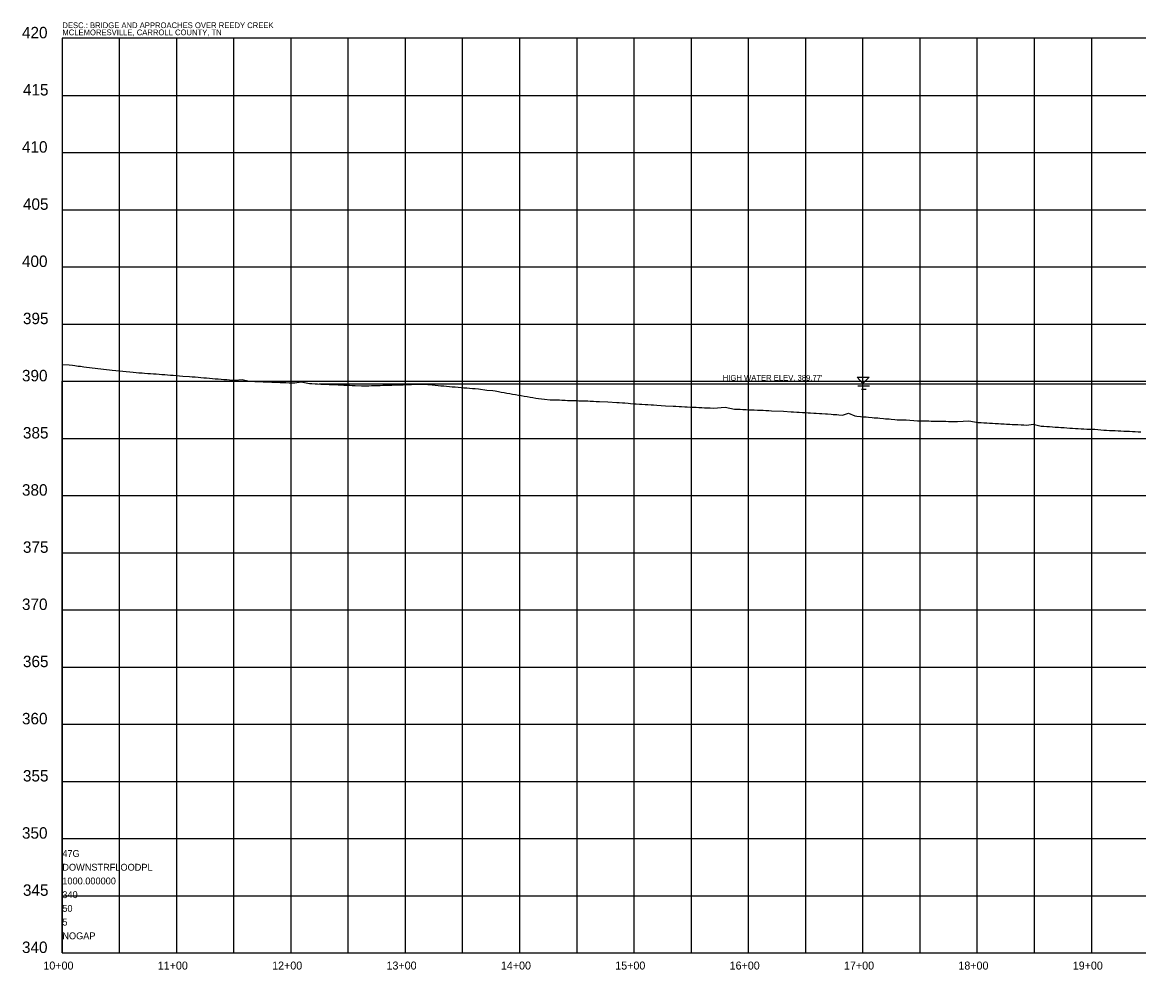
# Model space of a CAD drawing. Extents: x 1189978 to 1314812, y 571533 to 629339.
# Drawn here: x 1227570 to 1228546, y 623630 to 624459 of the extents above; entities that cross this region are included whole.
import ezdxf

# ---------------------------------------------------------------- set-up
doc = ezdxf.new("R2010")
doc.units = 0
for name, color, linetype in [('DESIGN - SHEET - Corner Text', 7, 'Continuous'), ('DESIGN - SHEET - Light Grid', 7, 'Continuous'), ('SURVEY - DRAINAGE - Pipes and Culverts Text', 7, 'Continuous'), ('SURVEY - PROFILE - Drainage - Bridge Hydraulic Data with Text', 7, 'Continuous'), ('SURVEY - PROFILE - Project Information and Notes', 7, 'Continuous')]:
    doc.layers.add(name, color=color, linetype=linetype)

msp = doc.modelspace()

# ---------------------------------------------------------------- linework, layer by layer
at = {"layer": 'DESIGN - SHEET - Light Grid'}
for p, q in [((1231404.88, 624444.99), (1227604.88, 624444.99)), ((1227604.88, 624444.99), (1227604.88, 623644.99)), ((1227654.88, 623644.99), (1227654.88, 624444.99)), ((1227704.88, 623644.99), (1227704.88, 624444.99)), ((1227754.88, 623644.99), (1227754.88, 624444.99)), ((1227804.88, 623644.99), (1227804.88, 624444.99)), ((1227854.88, 623644.99), (1227854.88, 624444.99)), ((1227904.88, 623644.99), (1227904.88, 624444.99)), ((1227954.88, 623644.99), (1227954.88, 624444.99)), ((1228004.88, 623644.99), (1228004.88, 624444.99)), ((1228054.88, 623644.99), (1228054.88, 624444.99)), ((1228104.88, 623644.99), (1228104.88, 624444.99)), ((1228154.88, 623644.99), (1228154.88, 624444.99)), ((1228204.88, 623644.99), (1228204.88, 624444.99)), ((1228254.88, 623644.99), (1228254.88, 624444.99)), ((1228304.88, 623644.99), (1228304.88, 624444.99)), ((1228354.88, 623644.99), (1228354.88, 624444.99)), ((1228404.88, 623644.99), (1228404.88, 624444.99)), ((1228454.88, 623644.99), (1228454.88, 624444.99)), ((1228504.88, 623644.99), (1228504.88, 624444.99)), ((1227604.88, 624394.99), (1231404.88, 624394.99)), ((1227604.88, 624344.99), (1231404.88, 624344.99)), ((1227604.88, 624294.99), (1231404.88, 624294.99)), ((1227604.88, 624244.99), (1231404.88, 624244.99)), ((1227604.88, 624194.99), (1231404.88, 624194.99)), ((1227604.88, 623644.99), (1227604.88, 624144.99)), ((1227604.88, 624144.99), (1231404.88, 624144.99)), ((1227604.88, 624094.99), (1231404.88, 624094.99)), ((1227604.88, 624044.99), (1231404.88, 624044.99)), ((1227604.88, 623994.99), (1231404.88, 623994.99)), ((1227604.88, 623944.99), (1231404.88, 623944.99)), ((1227604.88, 623894.99), (1231404.88, 623894.99)), ((1227604.88, 623844.99), (1231404.88, 623844.99)), ((1227604.88, 623794.99), (1231404.88, 623794.99)), ((1227604.88, 623744.99), (1231404.88, 623744.99)), ((1227604.88, 623694.99), (1231404.88, 623694.99)), ((1227604.88, 623644.99), (1231398.82, 623644.99)), ((1227604.88, 623644.99), (1227604.88, 623644.99)), ((1227604.88, 623644.99), (1231404.88, 623644.99))]:
    msp.add_line(p, q, dxfattribs=at)
at = {"layer": 'SURVEY - DRAINAGE - Pipes and Culverts Text'}
for p, q in [((1228299.7, 624148.55), (1228310.19, 624148.75)), ((1228299.7, 624148.55), (1228310.19, 624148.75)), ((1228304.88, 624142.96), (1228299.7, 624148.55)), ((1228304.88, 624142.96), (1228299.7, 624148.55)), ((1228310.19, 624148.75), (1228304.88, 624142.96)), ((1228310.19, 624148.75), (1228304.88, 624142.96)), ((1227829.3, 624142.69), (1231224.2, 624142.69)), ((1228300.52, 624140.93), (1228310.6, 624140.93)), ((1228300.52, 624140.93), (1228310.6, 624140.93)), ((1228303.61, 624138.26), (1228307.72, 624138.26)), ((1228303.61, 624138.26), (1228307.72, 624138.26))]:
    msp.add_line(p, q, dxfattribs=at)
at = {"layer": 'SURVEY - PROFILE - Drainage - Bridge Hydraulic Data with Text'}
msp.add_lwpolyline([(1227604.88, 624159.74), (1227610.85, 624159.41), (1227613.66, 624159), (1227615.87, 624158.77), (1227618.61, 624158.37), (1227620.89, 624158.13), (1227623.56, 624157.75), (1227625.91, 624157.5), (1227628.51, 624157.13), (1227630.93, 624156.88), (1227633.46, 624156.52), (1227635.94, 624156.26), (1227638.42, 624155.91), (1227640.96, 624155.65), (1227643.38, 624155.31), (1227645.98, 624155.04), (1227648.34, 624154.71), (1227657.87, 624153.86), (1227666.83, 624152.91), (1227669.55, 624152.68), (1227671.84, 624152.54), (1227674.54, 624152.31), (1227676.84, 624152.16), (1227679.53, 624151.94), (1227681.85, 624151.79), (1227684.52, 624151.56), (1227686.85, 624151.42), (1227689.51, 624151.19), (1227691.86, 624151.04), (1227694.49, 624150.82), (1227696.87, 624150.67), (1227699.48, 624150.45), (1227701.88, 624150.3), (1227704.47, 624150.08), (1227710.18, 624149.5), (1227716.09, 624149.21), (1227718.54, 624148.95), (1227721.08, 624148.8), (1227723.55, 624148.54), (1227726.07, 624148.39), (1227728.57, 624148.12), (1227731.07, 624147.97), (1227733.59, 624147.7), (1227736.06, 624147.56), (1227738.61, 624147.29), (1227741.05, 624147.14), (1227743.62, 624146.87), (1227746.05, 624146.72), (1227748.64, 624146.44), (1227751.04, 624146.3), (1227753.65, 624146.02), (1227756.04, 624145.87), (1227762.17, 624146.66), (1227768.13, 624145.1), (1227770.69, 624144.98), (1227773.15, 624144.9), (1227775.65, 624144.78), (1227778.16, 624144.71), (1227780.61, 624144.59), (1227783.17, 624144.52), (1227785.56, 624144.4), (1227788.19, 624144.32), (1227790.52, 624144.21), (1227793.2, 624144.13), (1227795.48, 624144.03), (1227798.21, 624143.95), (1227800.44, 624143.84), (1227803.22, 624143.76), (1227805.4, 624143.66), (1227808.24, 624143.58), (1227813.78, 624144.48), (1227821.01, 624143.07), (1227823.11, 624142.96), (1227825.99, 624142.85), (1227828.12, 624142.74), (1227830.97, 624142.63), (1227833.13, 624142.51), (1227835.96, 624142.41), (1227838.14, 624142.29), (1227840.94, 624142.19), (1227843.14, 624142.07), (1227845.92, 624141.96), (1227848.15, 624141.85), (1227850.9, 624141.74), (1227853.16, 624141.62), (1227855.88, 624141.52), (1227858.17, 624141.4), (1227860.86, 624141.29), (1227866.39, 624141.17), (1227872.86, 624141.18), (1227875.22, 624141.31), (1227877.86, 624141.32), (1227880.22, 624141.45), (1227882.85, 624141.46), (1227885.22, 624141.58), (1227887.85, 624141.6), (1227890.21, 624141.72), (1227892.85, 624141.74), (1227895.21, 624141.86), (1227897.84, 624141.88), (1227900.21, 624142), (1227902.84, 624142.03), (1227905.21, 624142.14), (1227907.84, 624142.17), (1227910.21, 624142.28), (1227920.26, 624142.41), (1227928.34, 624141.87), (1227930.9, 624141.57), (1227933.37, 624141.42), (1227935.89, 624141.13), (1227938.41, 624140.98), (1227940.88, 624140.69), (1227943.44, 624140.54), (1227945.86, 624140.26), (1227948.48, 624140.11), (1227950.85, 624139.83), (1227953.51, 624139.68), (1227955.84, 624139.41), (1227958.55, 624139.26), (1227960.82, 624139), (1227963.59, 624138.84), (1227965.81, 624138.59), (1227968.63, 624138.43), (1227976, 624137.11), (1227981.15, 624136.89), (1227983.37, 624136.53), (1227986.15, 624136.02), (1227988.45, 624135.64), (1227991.16, 624135.15), (1227993.53, 624134.76), (1227996.16, 624134.29), (1227998.61, 624133.88), (1228001.16, 624133.42), (1228003.69, 624133.01), (1228006.16, 624132.56), (1228008.78, 624132.13), (1228011.16, 624131.7), (1228013.86, 624131.26), (1228016.16, 624130.85), (1228018.94, 624130.39), (1228021.16, 624129.99), (1228026.58, 624129.27), (1228031.53, 624128.89), (1228034.43, 624128.85), (1228036.53, 624128.71), (1228039.43, 624128.67), (1228041.53, 624128.53), (1228044.43, 624128.49), (1228046.53, 624128.36), (1228049.43, 624128.31), (1228051.53, 624128.18), (1228054.44, 624128.13), (1228056.52, 624128), (1228059.44, 624127.96), (1228061.52, 624127.83), (1228064.44, 624127.78), (1228066.52, 624127.65), (1228069.44, 624127.6), (1228071.52, 624127.48), (1228074.44, 624127.43), (1228081.85, 624127.04), (1228089.6, 624126.5), (1228091.66, 624126.41), (1228094.6, 624126.15), (1228096.66, 624126.06), (1228099.6, 624125.79), (1228101.67, 624125.71), (1228104.6, 624125.44), (1228106.67, 624125.36), (1228109.59, 624125.09), (1228111.67, 624125), (1228114.59, 624124.74), (1228116.67, 624124.65), (1228119.59, 624124.39), (1228121.67, 624124.3), (1228124.59, 624124.04), (1228132.21, 624123.66), (1228139.08, 624123.23), (1228141.19, 624123.15), (1228144.08, 624122.98), (1228146.21, 624122.9), (1228149.08, 624122.74), (1228151.22, 624122.66), (1228154.08, 624122.49), (1228156.24, 624122.41), (1228159.08, 624122.25), (1228161.25, 624122.17), (1228164.08, 624122.01), (1228166.26, 624121.93), (1228169.08, 624121.77), (1228171.28, 624121.69), (1228174.08, 624121.53), (1228184.47, 624122.25), (1228192.66, 624120.73), (1228194.88, 624120.58), (1228197.67, 624120.51), (1228199.88, 624120.37), (1228202.68, 624120.3), (1228204.88, 624120.15), (1228207.69, 624120.08), (1228209.87, 624119.94), (1228212.7, 624119.87), (1228214.87, 624119.73), (1228217.71, 624119.65), (1228219.87, 624119.52), (1228222.72, 624119.44), (1228224.87, 624119.31), (1228235.34, 624118.93), (1228242.03, 624118.41), (1228244.09, 624118.35), (1228247.03, 624118.1), (1228249.06, 624118.04), (1228252.03, 624117.79), (1228254.03, 624117.72), (1228257.03, 624117.47), (1228259, 624117.41), (1228262.03, 624117.15), (1228263.97, 624117.09), (1228267.03, 624116.82), (1228268.94, 624116.76), (1228272.03, 624116.49), (1228273.91, 624116.44), (1228277.03, 624116.16), (1228278.88, 624116.11), (1228282.03, 624115.83), (1228283.85, 624115.77), (1228287.04, 624115.49), (1228292.31, 624117.03), (1228297.82, 624114.67), (1228299.58, 624114.46), (1228302.81, 624114.24), (1228304.59, 624114.03), (1228307.81, 624113.8), (1228309.6, 624113.59), (1228312.81, 624113.37), (1228314.62, 624113.15), (1228317.8, 624112.93), (1228319.63, 624112.71), (1228322.8, 624112.49), (1228324.64, 624112.27), (1228327.8, 624112.05), (1228329.66, 624111.83), (1228332.79, 624111.61), (1228334.67, 624111.39), (1228342.79, 624111.23), (1228352.46, 624110.52), (1228354.42, 624110.49), (1228357.46, 624110.41), (1228359.45, 624110.38), (1228362.46, 624110.31), (1228364.48, 624110.28), (1228367.45, 624110.2), (1228369.5, 624110.17), (1228372.45, 624110.1), (1228374.53, 624110.07), (1228377.45, 624110), (1228379.55, 624109.96), (1228382.45, 624109.89), (1228384.57, 624109.86), (1228387.44, 624109.79), (1228397.6, 624110.44), (1228405.5, 624109.11), (1228408.29, 624108.97), (1228410.49, 624108.82), (1228413.29, 624108.68), (1228415.48, 624108.53), (1228418.29, 624108.39), (1228420.48, 624108.24), (1228423.29, 624108.1), (1228425.47, 624107.95), (1228428.29, 624107.8), (1228430.46, 624107.66), (1228433.29, 624107.51), (1228435.45, 624107.37), (1228438.29, 624107.22), (1228440.44, 624107.08), (1228443.29, 624106.93), (1228445.44, 624106.79), (1228448.29, 624106.65), (1228453.74, 624107.44), (1228460.81, 624105.83), (1228462.97, 624105.7), (1228465.78, 624105.49), (1228467.98, 624105.36), (1228470.76, 624105.15), (1228472.99, 624105.03), (1228475.73, 624104.81), (1228478.01, 624104.69), (1228480.71, 624104.48), (1228483.02, 624104.35), (1228485.68, 624104.15), (1228488.03, 624104.02), (1228490.65, 624103.82), (1228493.05, 624103.69), (1228495.63, 624103.49), (1228498.06, 624103.36), (1228500.6, 624103.16), (1228507.5, 624103.12), (1228512.93, 624102.48), (1228515.47, 624102.33), (1228517.93, 624102.24), (1228520.48, 624102.08), (1228522.93, 624101.99), (1228525.48, 624101.84), (1228527.93, 624101.75), (1228530.49, 624101.6), (1228532.93, 624101.51), (1228535.49, 624101.35), (1228537.92, 624101.26), (1228540.5, 624101.11), (1228542.92, 624101.02), (1228545.51, 624100.86), (1228547.92, 624100.77)], dxfattribs=at)

# ---------------------------------------------------------------- texts
at = {"layer": 'DESIGN - SHEET - Corner Text'}
for s, height, p in [('420', 10, (1227569.6, 624444.99)), ('415', 10, (1227570.46, 624394.99)), ('410', 10, (1227569.6, 624344.99)), ('405', 10, (1227570.46, 624294.99)), ('400', 10, (1227569.6, 624244.99)), ('395', 10, (1227570.46, 624194.99)), ('390', 10, (1227569.6, 624144.99)), ('385', 10, (1227570.46, 624094.99)), ('380', 10, (1227569.6, 624044.99)), ('375', 10, (1227570.46, 623994.99)), ('370', 10, (1227569.6, 623944.99)), ('365', 10, (1227570.46, 623894.99)), ('360', 10, (1227569.6, 623844.99)), ('355', 10, (1227570.46, 623794.99)), ('350', 10, (1227569.6, 623744.99)), ('345', 10, (1227570.46, 623694.99)), ('340', 10, (1227569.6, 623644.99)), ('10+00', 7, (1227588.33, 623630.49)), ('11+00', 7, (1227688.33, 623630.49)), ('12+00', 7, (1227788.33, 623630.49)), ('13+00', 7, (1227888.33, 623630.49)), ('14+00', 7, (1227988.33, 623630.49)), ('15+00', 7, (1228088.33, 623630.49)), ('16+00', 7, (1228188.33, 623630.49)), ('17+00', 7, (1228288.33, 623630.49)), ('18+00', 7, (1228388.33, 623630.49)), ('19+00', 7, (1228488.33, 623630.49))]:
    msp.add_text(s, height=height, dxfattribs=at).set_placement(p)
at = {"layer": 'DESIGN - SHEET - Light Grid'}
for s, p in [('47G', (1227604.88, 623728.99)), ('DOWNSTRFLOODPL', (1227604.88, 623716.99)), ('1000.000000', (1227604.88, 623704.99)), ('340', (1227604.88, 623692.99)), ('50', (1227604.88, 623680.99)), ('5', (1227604.88, 623668.99)), ('NOGAP', (1227604.88, 623656.99))]:
    msp.add_text(s, height=6, dxfattribs=at).set_placement(p)
at = {"layer": 'SURVEY - PROFILE - Drainage - Bridge Hydraulic Data with Text'}
msp.add_text("HIGH WATER ELEV. 389.77'", height=5, dxfattribs=at).set_placement((1228182.34, 624145.55))
at = {"layer": 'SURVEY - PROFILE - Project Information and Notes'}
for s, p in [('DESC.: BRIDGE AND APPROACHES OVER REEDY CREEK', (1227604.92, 624453.91)), ('MCLEMORESVILLE, CARROLL COUNTY, TN', (1227604.92, 624447.69))]:
    msp.add_text(s, height=5, dxfattribs=at).set_placement(p)

doc.saveas('drawing.dxf')
